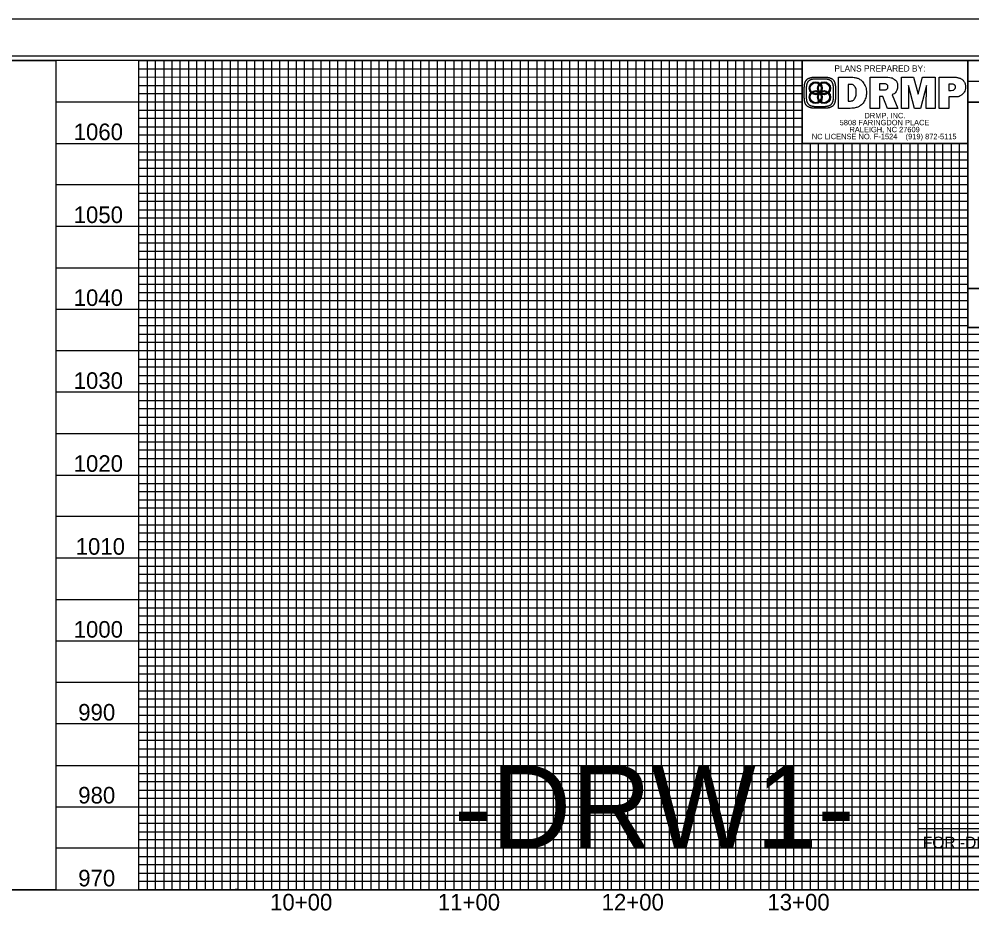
# Model space of a CAD drawing. Extents: x 1260439 to 1262228, y 742196 to 743296.
# Drawn here: x 1261333 to 1261908, y 742752 to 743296 of the extents above; entities that cross this region are included whole.
import ezdxf

# ---------------------------------------------------------------- set-up
doc = ezdxf.new("R2010")
doc.units = 0
for name, color, linetype in [('Exist Vertical Profile Horizontal Axis Label Major', 7, 'Continuous'), ('Exist Vertical Profile Vertical Axis Label', 7, 'Continuous'), ('Pattern 1', 7, 'Continuous'), ('Pattern 2', 7, 'Continuous'), ('Prop Grid Mask', 7, 'Continuous'), ('Prop PFL Text', 7, 'Continuous'), ('Scratch_Level_0', 7, 'Continuous'), ('Sheet Cutting Line CELL', 7, 'Continuous'), ('Sheet Data Field CELL', 7, 'Continuous'), ('Sheet Layout Profile Border Port 1', 7, 'Continuous'), ('Sheet Plot Border Inside CELL', 7, 'Continuous'), ('Sheet Plot Border Outside CELL', 7, 'Continuous'), ('Sheet Profile CELL', 7, 'Continuous'), ('Sheet Profile Grid Major CELL', 7, 'Continuous'), ('Sheet Profile Grid Middle CELL', 7, 'Continuous'), ('Sheet Profile Grid Minor CELL', 7, 'Continuous'), ('Sheet Sticker Exception Certification CELL', 7, 'Continuous')]:
    doc.layers.add(name, color=color, linetype=linetype)

msp = doc.modelspace()

# ---------------------------------------------------------------- linework, layer by layer
at = {"layer": 'Pattern 1'}
for p, q in [((1261813.81, 743260.72), (1261819.26, 743260.72)), ((1261865.69, 743241.9), (1261865.69, 743260.7)), ((1261865.69, 743260.7), (1261873.08, 743260.7)), ((1261873.08, 743260.7), (1261875.9, 743250.43)), ((1261875.9, 743250.43), (1261878.38, 743260.7)), ((1261878.38, 743260.7), (1261886.1, 743260.7)), ((1261886.1, 743260.7), (1261886.1, 743241.9)), ((1261807.14, 743248.6), (1261807.14, 743254.05)), ((1261818.92, 743259.57), (1261814.14, 743259.57)), ((1261825.92, 743254.05), (1261825.92, 743248.6)), ((1261873.54, 743241.9), (1261869.89, 743255.69)), ((1261869.89, 743255.69), (1261870.08, 743241.9)), ((1261880.77, 743255.69), (1261877.19, 743241.9)), ((1261880.68, 743241.9), (1261880.77, 743255.69)), ((1261808.29, 743253.72), (1261808.29, 743248.94)), ((1261824.77, 743248.94), (1261824.77, 743253.72)), ((1261814.14, 743243.08), (1261818.92, 743243.08)), ((1261819.26, 743241.94), (1261813.81, 743241.94)), ((1261870.08, 743241.9), (1261865.69, 743241.9)), ((1261877.19, 743241.9), (1261873.54, 743241.9)), ((1261886.1, 743241.9), (1261880.68, 743241.9))]:
    msp.add_line(p, q, dxfattribs=at)
for points in [[(1261834.84, 743241.9), (1261827.86, 743241.9), (1261827.86, 743260.7), (1261835.09, 743260.7)], [(1261860.08, 743250.12), (1261863.47, 743241.9), (1261857.29, 743241.9), (1261854.51, 743249.03), (1261852.54, 743249.03), (1261852.54, 743241.9), (1261846.82, 743241.9), (1261846.82, 743260.7), (1261856, 743260.7)], [(1261897.59, 743248.75), (1261894.25, 743248.75), (1261894.25, 743241.9), (1261888.49, 743241.9), (1261888.49, 743260.7), (1261896.5, 743260.7)], [(1261835.09, 743256.38), (1261833.62, 743256.38), (1261833.62, 743246.3), (1261834.92, 743246.3)], [(1261855.19, 743256.69), (1261852.54, 743256.69), (1261852.54, 743253.01), (1261855.27, 743253.01)], [(1261896.15, 743256.45), (1261894.25, 743256.45), (1261894.25, 743252.76), (1261895.8, 743252.76)]]:
    msp.add_lwpolyline(points, dxfattribs=at)
for points, degree in [([(1261807.14, 743254.05), (1261807.14, 743257.72), (1261810.14, 743260.72), (1261813.81, 743260.72)], 2), ([(1261819.26, 743260.72), (1261822.92, 743260.72), (1261825.92, 743257.72), (1261825.92, 743254.05)], 2), ([(1261835.09, 743260.7), (1261836.23, 743260.7), (1261837.25, 743260.6), (1261838.15, 743260.39), (1261839.05, 743260.19), (1261839.83, 743259.88), (1261840.51, 743259.45), (1261841.79, 743258.64), (1261842.79, 743257.53), (1261843.5, 743256.1), (1261844.21, 743254.68), (1261844.57, 743253.08), (1261844.57, 743251.31), (1261844.57, 743249.74), (1261844.26, 743248.27), (1261843.63, 743246.9), (1261843, 743245.54), (1261842.15, 743244.45), (1261841.07, 743243.64), (1261840.27, 743243.05), (1261839.36, 743242.61), (1261838.35, 743242.33), (1261837.34, 743242.05), (1261836.17, 743241.9), (1261834.84, 743241.9)], 3), ([(1261856, 743260.7), (1261858.46, 743260.7), (1261860.3, 743260.24), (1261861.53, 743259.33), (1261862.75, 743258.42), (1261863.36, 743257.04), (1261863.36, 743255.21), (1261863.36, 743253.94), (1261863.08, 743252.87), (1261862.52, 743251.99), (1261861.96, 743251.12), (1261861.15, 743250.49), (1261860.08, 743250.12)], 3), ([(1261896.5, 743260.7), (1261897.76, 743260.7), (1261898.8, 743260.62), (1261899.62, 743260.47), (1261900.44, 743260.31), (1261901.13, 743260.07), (1261901.68, 743259.73), (1261902.56, 743259.18), (1261903.23, 743258.48), (1261903.68, 743257.63), (1261904.14, 743256.78), (1261904.36, 743255.82), (1261904.36, 743254.74), (1261904.36, 743252.95), (1261903.74, 743251.51), (1261902.5, 743250.41), (1261901.25, 743249.3), (1261899.62, 743248.75), (1261897.59, 743248.75)], 3), ([(1261814.14, 743259.57), (1261810.92, 743259.57), (1261808.29, 743256.93), (1261808.29, 743253.72)], 2), ([(1261824.77, 743253.72), (1261824.77, 743256.93), (1261822.14, 743259.57), (1261818.92, 743259.57)], 2), ([(1261834.92, 743246.3), (1261836, 743246.3), (1261836.86, 743246.76), (1261837.51, 743247.69), (1261838.16, 743248.61), (1261838.49, 743249.85), (1261838.49, 743251.39), (1261838.49, 743252.92), (1261838.18, 743254.13), (1261837.56, 743255.03), (1261836.95, 743255.93), (1261836.13, 743256.38), (1261835.09, 743256.38)], 3), ([(1261855.27, 743253.01), (1261855.94, 743253.01), (1261856.49, 743253.18), (1261856.91, 743253.53), (1261857.33, 743253.87), (1261857.55, 743254.31), (1261857.55, 743254.85), (1261857.55, 743255.47), (1261857.35, 743255.93), (1261856.96, 743256.23), (1261856.57, 743256.53), (1261855.98, 743256.69), (1261855.19, 743256.69)], 3), ([(1261895.8, 743252.76), (1261896.58, 743252.76), (1261897.18, 743252.93), (1261897.62, 743253.25), (1261898.05, 743253.58), (1261898.27, 743254.03), (1261898.27, 743254.61), (1261898.27, 743255.2), (1261898.08, 743255.66), (1261897.72, 743255.98), (1261897.36, 743256.29), (1261896.84, 743256.45), (1261896.15, 743256.45)], 3), ([(1261813.81, 743241.94), (1261810.14, 743241.94), (1261807.14, 743244.94), (1261807.14, 743248.6)], 2), ([(1261808.29, 743248.94), (1261808.29, 743245.72), (1261810.92, 743243.08), (1261814.14, 743243.08)], 2), ([(1261818.92, 743243.08), (1261822.14, 743243.08), (1261824.77, 743245.72), (1261824.77, 743248.94)], 2), ([(1261825.92, 743248.6), (1261825.92, 743244.94), (1261822.92, 743241.94), (1261819.26, 743241.94)], 2)]:
    msp.add_open_spline(points, degree=degree, dxfattribs=at)
at = {"layer": 'Pattern 2'}
for centre, radius in [((1261814.03, 743253.99), 3.93), ((1261814.03, 743253.99), 3.34), ((1261819.03, 743253.99), 3.93), ((1261819.03, 743253.99), 3.34), ((1261814.03, 743248.66), 3.93), ((1261814.03, 743248.66), 3.34), ((1261819.03, 743248.66), 3.93), ((1261819.03, 743248.66), 3.34)]:
    msp.add_circle(centre, radius, dxfattribs=at)
at = {"layer": 'Prop Grid Mask'}
msp.add_lwpolyline([(1261875.75, 742807.74), (1262035.75, 742807.74), (1262035.75, 742790.74), (1261875.75, 742790.74)], close=True, dxfattribs=at)
at = {"layer": 'Scratch_Level_0'}
for points in [[(1260755.75, 743270.74), (1261355.75, 743270.74), (1261355.75, 742770.74), (1260755.75, 742770.74)], [(1261405.75, 743270.74), (1261805.75, 743270.74), (1261805.75, 743220.74), (1261905.75, 743220.74), (1261905.7, 743109.69), (1262055.75, 743109.69), (1262055.75, 742770.74), (1261405.75, 742770.74)], [(1261905.7, 743270.74), (1261905.7, 743220.74), (1261805.75, 743220.74), (1261805.75, 743270.74)], [(1261905.7, 743270.74), (1261905.7, 743220.74), (1261805.75, 743220.74), (1261805.75, 743270.74)]]:
    msp.add_lwpolyline(points, close=True, dxfattribs=at)
at = {"layer": 'Sheet Cutting Line CELL'}
msp.add_line((1262122.75, 743295.74), (1260438.75, 743295.74), dxfattribs=at)
at = {"layer": 'Sheet Layout Profile Border Port 1'}
msp.add_lwpolyline([(1261555.75, 742770.74), (1261805.75, 742770.74), (1261805.75, 743270.74), (1261555.75, 743270.74)], close=True, dxfattribs=at)
msp.add_lwpolyline([(1260655.75, 743109.69), (1260655.75, 742770.74), (1262055.75, 742770.74), (1262055.75, 743109.69)], dxfattribs=at)
msp.add_lwpolyline([(1260655.75, 743109.69), (1260655.75, 742770.74), (1262055.75, 742770.74), (1262055.75, 743109.69)], dxfattribs=at)
msp.add_lwpolyline([(1260655.75, 743109.69), (1260655.75, 742770.74), (1262055.75, 742770.74), (1262055.75, 743109.69)], dxfattribs=at)
at = {"layer": 'Sheet Plot Border Inside CELL'}
msp.add_lwpolyline([(1260451.75, 742218.19), (1262118.25, 742218.19), (1262118.25, 743273.29), (1260451.75, 743273.29)], close=True, dxfattribs=at)
at = {"layer": 'Sheet Plot Border Outside CELL'}
msp.add_lwpolyline([(1260438.75, 742195.74), (1262122.75, 742195.74), (1262122.75, 743295.74), (1260438.75, 743295.74)], close=True, dxfattribs=at)
at = {"layer": 'Sheet Profile CELL'}
for p, q in [((1261905.7, 743258.19), (1262105.75, 743258.19)), ((1260605.75, 742770.74), (1262105.75, 742770.74))]:
    msp.add_line(p, q, dxfattribs=at)
for points in [[(1262105.75, 743270.74), (1260605.75, 743270.74), (1260605.75, 742220.74), (1262105.75, 742220.74)], [(1261905.7, 743270.74), (1262105.75, 743270.74), (1262105.75, 743245.69), (1261905.7, 743245.69)], [(1261905.7, 743245.69), (1262005.75, 743245.69), (1262005.75, 743133.19), (1261905.7, 743133.19)]]:
    msp.add_lwpolyline(points, close=True, dxfattribs=at)
at = {"layer": 'Sheet Profile Grid Major CELL'}
for p, q in [((1261355.75, 743270.74), (1261355.75, 742770.74)), ((1261405.75, 742770.74), (1261405.75, 743270.74)), ((1261405.75, 743270.74), (1261455.75, 743270.74)), ((1261455.75, 743270.74), (1261455.75, 742770.74)), ((1261505.75, 742770.74), (1261505.75, 743270.74)), ((1261505.75, 743270.74), (1261555.75, 743270.74)), ((1261555.75, 743270.74), (1261555.75, 742770.74)), ((1261605.75, 742770.74), (1261605.75, 743270.74)), ((1261605.75, 743270.74), (1261655.75, 743270.74)), ((1261655.75, 743270.74), (1261655.75, 742770.74)), ((1261705.75, 742770.74), (1261705.75, 743270.74)), ((1261705.75, 743270.74), (1261755.75, 743270.74)), ((1261755.75, 743270.74), (1261755.75, 742770.74)), ((1261805.75, 742770.74), (1261805.75, 743270.74)), ((1261855.75, 743220.74), (1261855.75, 742770.74)), ((1261905.75, 742770.74), (1261905.75, 743220.74)), ((1261355.75, 742770.74), (1261405.75, 742770.74)), ((1261455.75, 742770.74), (1261505.75, 742770.74)), ((1261555.75, 742770.74), (1261605.75, 742770.74)), ((1261655.75, 742770.74), (1261705.75, 742770.74)), ((1261755.75, 742770.74), (1261805.75, 742770.74)), ((1261855.75, 742770.74), (1261905.75, 742770.74))]:
    msp.add_line(p, q, dxfattribs=at)
for points in [[(1261355.75, 743220.74), (1261905.75, 743220.74)], [(1261905.75, 743170.74), (1261355.75, 743170.74)], [(1261355.75, 743120.74), (1261905.75, 743120.74)], [(1262105.75, 743070.74), (1261355.75, 743070.74)], [(1261355.75, 743020.74), (1262105.75, 743020.74)], [(1262105.75, 742970.74), (1261355.75, 742970.74)], [(1261355.75, 742920.74), (1262105.75, 742920.74)], [(1262105.75, 742870.74), (1261355.75, 742870.74)], [(1261355.75, 742820.74), (1262105.75, 742820.74)]]:
    msp.add_lwpolyline(points, dxfattribs=at)
at = {"layer": 'Sheet Profile Grid Middle CELL'}
for p, q in [((1261430.75, 742770.74), (1261430.75, 743270.74)), ((1261430.75, 743270.74), (1261480.75, 743270.74)), ((1261480.75, 743270.74), (1261480.75, 742770.74)), ((1261530.75, 742770.74), (1261530.75, 743270.74)), ((1261530.75, 743270.74), (1261580.75, 743270.74)), ((1261580.75, 743270.74), (1261580.75, 742770.74)), ((1261630.75, 742770.74), (1261630.75, 743270.74)), ((1261630.75, 743270.74), (1261680.75, 743270.74)), ((1261680.75, 743270.74), (1261680.75, 742770.74)), ((1261730.75, 742770.74), (1261730.75, 743270.74)), ((1261730.75, 743270.74), (1261780.75, 743270.74)), ((1261780.75, 743270.74), (1261780.75, 742770.74)), ((1261355.75, 743245.74), (1261805.75, 743245.74)), ((1261830.75, 742770.74), (1261830.75, 743220.74)), ((1261880.75, 743220.74), (1261880.75, 742770.74)), ((1261380.75, 742770.74), (1261430.75, 742770.74)), ((1261480.75, 742770.74), (1261530.75, 742770.74)), ((1261580.75, 742770.74), (1261630.75, 742770.74)), ((1261680.75, 742770.74), (1261730.75, 742770.74)), ((1261780.75, 742770.74), (1261830.75, 742770.74)), ((1261880.75, 742770.74), (1261930.75, 742770.74))]:
    msp.add_line(p, q, dxfattribs=at)
for points in [[(1261905.75, 743195.74), (1261355.75, 743195.74)], [(1261355.75, 743145.74), (1261905.75, 743145.74)], [(1262105.75, 743095.74), (1261355.75, 743095.74)], [(1261355.75, 743045.74), (1261930.75, 743045.74)], [(1262105.75, 742995.74), (1261355.75, 742995.74)], [(1261355.75, 742945.74), (1262105.75, 742945.74)], [(1262105.75, 742895.74), (1261355.75, 742895.74)], [(1261355.75, 742845.74), (1262105.75, 742845.74)], [(1262105.75, 742795.74), (1261355.75, 742795.74)]]:
    msp.add_lwpolyline(points, dxfattribs=at)
at = {"layer": 'Sheet Profile Grid Minor CELL'}
for p, q in [((1261405.75, 743265.74), (1261805.75, 743265.74)), ((1261800.75, 742770.74), (1261800.75, 743270.74)), ((1261805.75, 743260.71), (1261405.75, 743260.6)), ((1261405.75, 743255.74), (1261805.75, 743255.74)), ((1261810.75, 743220.74), (1261810.75, 742770.74)), ((1261815.75, 742770.74), (1261815.75, 743220.74)), ((1261820.75, 743220.74), (1261820.75, 742770.74)), ((1261825.75, 742770.74), (1261825.75, 743220.74)), ((1261835.75, 743220.74), (1261835.75, 742770.74)), ((1261840.75, 742770.74), (1261840.75, 743220.74)), ((1261845.75, 743220.74), (1261845.75, 742770.74)), ((1261850.75, 742770.74), (1261850.75, 743220.74)), ((1261860.75, 743220.74), (1261860.75, 742770.74)), ((1261865.75, 742770.74), (1261865.75, 743220.74)), ((1261870.75, 743220.74), (1261870.75, 742770.74)), ((1261875.75, 742770.74), (1261875.75, 743220.74)), ((1261885.75, 743220.74), (1261885.75, 742770.74)), ((1261890.75, 742770.74), (1261890.75, 743220.74)), ((1261895.75, 743220.74), (1261895.75, 742770.74)), ((1261900.75, 742770.74), (1261900.75, 743220.74)), ((1261905.7, 743135.74), (1261405.75, 743135.74)), ((1261905.75, 743130.74), (1261405.75, 743130.74)), ((1261905.75, 743125.74), (1261405.75, 743125.74)), ((1261405.75, 743115.74), (1261905.75, 743115.74)), ((1261905.75, 743110.74), (1261405.75, 743110.74)), ((1261405.75, 743105.74), (1262055.75, 743105.74)), ((1262055.75, 743085.74), (1261405.75, 743085.74)), ((1261405.75, 743080.74), (1262055.75, 743080.74)), ((1262055.75, 743060.74), (1261405.75, 743060.74)), ((1261405.75, 743055.74), (1262055.75, 743055.74)), ((1262055.75, 743035.74), (1261405.75, 743035.74)), ((1261405.75, 743030.74), (1262055.75, 743030.74)), ((1262055.75, 743025.74), (1261405.75, 743025.74)), ((1261405.75, 743015.74), (1262055.75, 743015.74)), ((1262055.75, 743010.74), (1261405.75, 743010.74)), ((1261405.75, 743005.74), (1262055.75, 743005.74)), ((1262055.75, 743000.74), (1261405.75, 743000.74)), ((1261405.75, 742990.74), (1262055.75, 742990.74)), ((1262055.75, 742985.74), (1261405.75, 742985.74)), ((1261405.75, 742980.74), (1262055.75, 742980.74)), ((1262055.75, 742975.74), (1261405.75, 742975.74)), ((1261405.75, 742965.74), (1262055.75, 742965.74)), ((1262055.75, 742960.74), (1261405.75, 742960.74)), ((1261405.75, 742955.74), (1262055.75, 742955.74)), ((1262055.75, 742950.74), (1261405.75, 742950.74)), ((1261405.75, 742940.74), (1262055.75, 742940.74)), ((1262055.75, 742935.74), (1261405.75, 742935.74)), ((1261405.75, 742930.74), (1262055.75, 742930.74)), ((1262055.75, 742925.74), (1261405.75, 742925.74)), ((1261405.75, 742915.74), (1262055.75, 742915.74)), ((1262055.75, 742910.74), (1261405.75, 742910.74)), ((1261405.75, 742905.74), (1262055.75, 742905.74)), ((1262055.75, 742900.74), (1261405.75, 742900.74)), ((1261405.75, 742890.74), (1262055.75, 742890.74)), ((1262055.75, 742885.74), (1261405.75, 742885.74)), ((1262055.75, 742880.74), (1261405.75, 742880.74)), ((1262055.75, 742875.74), (1261405.75, 742875.74)), ((1261405.75, 742865.74), (1262055.75, 742865.74)), ((1262055.75, 742860.74), (1261405.75, 742860.74)), ((1261405.75, 742855.74), (1262055.75, 742855.74)), ((1262055.75, 742850.74), (1261405.75, 742850.74)), ((1261405.75, 742840.74), (1262055.75, 742840.74)), ((1262055.75, 742835.74), (1261405.75, 742835.74)), ((1261405.75, 742830.74), (1262055.75, 742830.74)), ((1262055.75, 742825.74), (1261405.75, 742825.74)), ((1261405.75, 742815.74), (1262055.75, 742815.74)), ((1262055.75, 742810.74), (1261405.75, 742810.74)), ((1261405.75, 742805.74), (1262055.75, 742805.74)), ((1262055.75, 742800.74), (1261405.75, 742800.74)), ((1261405.75, 742790.74), (1262055.75, 742790.74)), ((1262055.75, 742785.74), (1261405.75, 742785.74)), ((1261405.75, 742780.74), (1262055.75, 742780.74)), ((1261795.75, 742770.74), (1261800.75, 742770.74)), ((1261810.75, 742770.74), (1261815.75, 742770.74)), ((1261820.75, 742770.74), (1261825.75, 742770.74)), ((1261835.75, 742770.74), (1261840.75, 742770.74)), ((1261845.75, 742770.74), (1261850.75, 742770.74)), ((1261860.75, 742770.74), (1261865.75, 742770.74)), ((1261870.75, 742770.74), (1261875.75, 742770.74)), ((1261885.75, 742770.74), (1261890.75, 742770.74)), ((1261895.75, 742770.74), (1261900.75, 742770.74))]:
    msp.add_line(p, q, dxfattribs=at)
for points in [[(1261405.75, 743270.74), (1261410.75, 743270.74), (1261410.75, 742770.74), (1261415.75, 742770.74), (1261415.75, 743270.74), (1261420.75, 743270.74), (1261420.75, 742770.74), (1261425.75, 742770.74), (1261425.75, 743270.74), (1261435.75, 743270.74), (1261435.75, 742770.74), (1261440.75, 742770.74), (1261440.75, 743270.74), (1261445.75, 743270.74), (1261445.75, 742770.74), (1261450.75, 742770.74), (1261450.75, 743270.74), (1261460.75, 743270.74), (1261460.75, 742770.74), (1261465.45, 742771.29), (1261465.75, 742770.74), (1261465.75, 743270.74), (1261470.75, 743270.74), (1261470.75, 742770.74), (1261475.75, 742770.74), (1261475.75, 743270.74), (1261485.75, 743270.74), (1261485.75, 742770.74), (1261490.75, 742770.74)], [(1261490.75, 742770.74), (1261490.75, 743270.74), (1261495.75, 743270.74), (1261495.75, 742770.74), (1261500.75, 742770.74), (1261500.75, 743270.74), (1261510.75, 743270.74), (1261510.75, 742770.74), (1261515.75, 742770.74), (1261515.75, 743270.74), (1261520.75, 743270.74), (1261520.75, 742770.74), (1261525.75, 742770.74), (1261525.75, 743270.74), (1261535.75, 743270.74), (1261535.75, 742770.74), (1261540.75, 742770.74), (1261540.75, 743270.74), (1261545.75, 743270.74), (1261545.75, 742770.74), (1261550.75, 742770.74), (1261550.75, 743270.74), (1261560.75, 743270.74), (1261560.75, 742770.74), (1261565.75, 742770.74), (1261565.75, 743270.74), (1261570.75, 743270.74), (1261570.75, 742770.74), (1261575.75, 742770.74), (1261575.75, 743270.74), (1261585.75, 743270.74), (1261585.75, 742770.74), (1261590.75, 742770.74), (1261590.75, 743270.74), (1261595.75, 743270.74), (1261595.75, 742770.74), (1261600.75, 742770.74), (1261600.75, 743270.74), (1261610.75, 743270.74), (1261610.75, 742770.74), (1261615.75, 742770.74), (1261615.75, 743270.74), (1261620.75, 743270.74), (1261620.75, 742770.74), (1261625.75, 742770.74), (1261625.75, 743270.74), (1261635.75, 743270.74), (1261635.75, 742770.74), (1261640.75, 742770.74), (1261640.75, 743270.74), (1261645.75, 743270.74), (1261645.75, 742770.74), (1261650.75, 742770.74), (1261650.75, 743270.74), (1261660.75, 743270.74), (1261660.75, 742770.74), (1261665.75, 742770.74), (1261665.75, 743270.74), (1261670.75, 743270.74), (1261670.75, 742770.74), (1261675.75, 742770.74), (1261675.75, 743270.74), (1261685.75, 743270.74), (1261685.75, 742770.74), (1261690.75, 742770.74), (1261690.75, 743270.74), (1261695.75, 743270.74), (1261695.75, 742770.74), (1261700.75, 742770.74), (1261700.75, 743270.74), (1261710.75, 743270.74), (1261710.75, 742770.74), (1261715.75, 742770.74), (1261715.75, 743270.74), (1261720.75, 743270.74), (1261720.75, 742770.74), (1261725.75, 742770.74), (1261725.75, 743270.74), (1261735.75, 743270.74), (1261735.75, 742770.74), (1261740.75, 742770.74), (1261740.75, 743270.74), (1261745.75, 743270.74), (1261745.75, 742770.74), (1261750.75, 742770.74), (1261750.75, 743270.74), (1261760.75, 743270.74), (1261760.75, 742770.74), (1261765.75, 742770.74), (1261765.75, 743270.74), (1261770.75, 743270.74), (1261770.75, 742770.74), (1261775.75, 742770.74), (1261775.75, 743270.74), (1261785.75, 743270.74), (1261785.75, 742770.74), (1261790.75, 742770.74), (1261790.75, 743270.74), (1261795.75, 743270.74), (1261795.75, 742770.74)], [(1261805.75, 743250.74), (1261405.75, 743250.74)], [(1261405.75, 743240.74), (1261805.75, 743240.74)], [(1261805.75, 743235.74), (1261405.75, 743235.74)], [(1261405.75, 743230.74), (1261805.75, 743230.74)], [(1261805.75, 743225.74), (1261405.75, 743225.74)], [(1261405.75, 743215.74), (1261905.75, 743215.74)], [(1261905.75, 743210.74), (1261405.75, 743210.74)], [(1261405.75, 743205.74), (1261905.75, 743205.74)], [(1261905.75, 743200.74), (1261405.75, 743200.74)], [(1261405.75, 743190.74), (1261905.75, 743190.74)], [(1261905.75, 743185.74), (1261405.75, 743185.74)], [(1261405.75, 743180.74), (1261905.75, 743180.74)], [(1261905.75, 743175.74), (1261405.75, 743175.74)], [(1261405.75, 743165.74), (1261905.75, 743165.74)], [(1261905.75, 743160.64), (1261405.75, 743160.64)], [(1261405.75, 743155.74), (1261905.75, 743155.74)], [(1261905.75, 743150.74), (1261405.75, 743150.74)], [(1261405.75, 743140.74), (1261905.75, 743140.74)], [(1262055.75, 743100.74), (1261405.75, 743100.74)], [(1261405.75, 743090.74), (1262055.75, 743090.74)], [(1262055.75, 743075.74), (1261405.75, 743075.74)], [(1261405.75, 743065.74), (1262055.75, 743065.74)], [(1262055.75, 743050.74), (1261405.75, 743050.74)], [(1261405.75, 743040.74), (1262055.75, 743040.74)], [(1262055.75, 742775.74), (1261405.75, 742775.74)]]:
    msp.add_lwpolyline(points, dxfattribs=at)
at = {"layer": 'Sheet Sticker Exception Certification CELL'}
for p, q in [((1261905.7, 743109.69), (1261905.7, 743133.19)), ((1261905.7, 743133.19), (1262105.74, 743133.19)), ((1262105.74, 743109.69), (1261905.7, 743109.69))]:
    msp.add_line(p, q, dxfattribs=at)

# ---------------------------------------------------------------- texts
at = {"layer": 'Exist Vertical Profile Horizontal Axis Label Major'}
for s, p in [('10+00', (1261484.88, 742758.24)), ('11+00', (1261586.08, 742758.24)), ('12+00', (1261684.88, 742758.24)), ('13+00', (1261784.88, 742758.24))]:
    msp.add_text(s, height=10, dxfattribs=at).set_placement(p)
at = {"layer": 'Exist Vertical Profile Vertical Axis Label'}
for s, p in [('1060', (1261366.43, 743222.74)), ('1050', (1261366.43, 743172.74)), ('1040', (1261366.43, 743122.74)), ('1030', (1261366.43, 743072.74)), ('1020', (1261366.43, 743022.74)), ('1010', (1261367.63, 742972.74)), ('1000', (1261366.43, 742922.74)), ('990', (1261369.19, 742872.74)), ('980', (1261369.19, 742822.74)), ('970', (1261369.19, 742772.74))]:
    msp.add_text(s, height=10, dxfattribs=at).set_placement(p)
at = {"layer": 'Pattern 2'}
msp.add_text('PLANS PREPARED BY:', height=3.75, rotation=360, dxfattribs=at).set_placement((1261825.28, 743264.07))
for s, p in [('DRMP, INC.', (1261843.44, 743235.9)), ('5808 FARINGDON PLACE', (1261828.47, 743231.7)), ('NC LICENSE NO. F-1524    (919) 872-5115', (1261811.66, 743223.29)), ('RALEIGH, NC 27609', (1261834.38, 743227.49))]:
    msp.add_text(s, height=3.25, dxfattribs=at).set_placement(p)
at = {"layer": 'Prop PFL Text'}
msp.add_text('FOR -DRW1- PLAN SEE SHEET 06', height=7, dxfattribs=at).set_placement((1261878.66, 742795.74))
at = {"layer": 'Sheet Data Field CELL'}
msp.add_text('-DRW1-', height=50, dxfattribs=at).set_placement((1261595.98, 742795.74))

doc.saveas('drawing.dxf')
